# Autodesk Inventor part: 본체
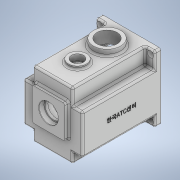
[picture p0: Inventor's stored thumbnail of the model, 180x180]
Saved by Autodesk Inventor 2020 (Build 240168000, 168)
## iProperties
Created: 2022-01
Part Number: 본체
Material: 일반
Document SubType Name: Modeling
Designer: user
Density: 1 g/cm^3
Appearance: 기본값
Author: user
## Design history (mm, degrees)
sketch "스케치5"
  geometry: L1 (-49, -55)-(49, -55); L2 (49, -55)-(49, 55); L3 (49, 55)-(-49, 55); L4 (-49, 55)-(-49, -55); L5 (-49, -55)-(49, 55); L6 (49, -55)-(-49, 55); 1 further point
  constraints: 12 end point, 2 midpoint, 2 parallel, 1 horizontal, 1 perpendicular
  dimensions: "d27" = 98 distance of L3.end L2.end; "d28" = 110 distance of L2.end L1.end
extrude "돌출6" new body sketch "스케치5" stored distance "d29" = 130; taper "d30" = 0 deg
sketch "스케치7"
  geometry: L1 (-49, 55)-(-49, -55) reference; L2 (-49, 55)-(-33, 55); L3 (-33, 55)-(-33, 28); L4 (-33, 28)-(-49, 28); L5 (-49, 28)-(-49, 55); L6 (49, 55)-(-49, 55) reference; L7 (49, 55)-(33, 55); L8 (33, 55)-(33, 28); L9 (33, 28)-(49, 28); L10 (49, 28)-(49, 55); L11 (49, -55)-(49, 55) reference; L12 (49, -55)-(33, -55); L13 (33, -55)-(33, -38); L14 (33, -38)-(49, -38); L15 (49, -38)-(49, -55); L16 (-49, -55)-(49, -55) reference; L17 (-49, -55)-(-33, -55); L18 (-33, -55)-(-33, -38); L19 (-33, -38)-(-49, -38); L20 (-49, -38)-(-49, -55); 6 further points
  constraints: 32 end point, 8 parallel, 4 horizontal, 4 perpendicular, 1 point on line
  dimensions: "d36" = 16 distance of L3.end L4.end; "d37" = 27 distance of L2.end L3.end; "d38" = 16 distance of L9.end L8.end; "d39" = 27 distance of L8.end L7.end; "d40" = 16 distance of L13.end L14.end; "d41" = 17 distance of L12.end L13.end; "d42" = 17 distance of L18.end L17.end
extrude "돌출8" cut sketch "스케치7" distance "d43" = 120; taper "d44" = 0 deg
sketch "스케치8"
  geometry: L1 (98, 0)-(0, 0) reference; L2 (49, 0)-(49, -40); L3 (49, -40)-(49, -89); C1 r 22.5 at (49, -40); C2 r 15 at (49, -89); 1 further point
  constraints: 4 end point, 2 centre point, 2 coincident, 1 midpoint, 1 point on line, 1 vertical
  dimensions: "d45" = 40 distance of L2.start L2.end; "d46" = 49 distance of L2.end L3.end; "d47" = 45 diameter of C1; "d48" = 30 diameter of C2
extrude "돌출9" join sketch "스케치8" distance "d49" = 5; taper "d50" = 0 deg
extrude "돌출10" join sketch "스케치8" distance "d51" = 10; taper "d52" = 0 deg
sketch "스케치9"
  geometry: L1 (0, 0)-(0, 11); L2 (33, -55)-(-33, -55) reference; L3 (0, -55)-(0, -5); L4 (0, 45)-(-23, 45); L5 (-23, 45)-(23, 45); L6 (23, 45)-(23, 33.249); L7 (-23, 33.249)-(-23, 45); A1 r 42 centre (0, -5) between (-25.375, 28.468) and (25.375, 28.468); A2 r 6 centre (-29, 33.249) between (-25.375, 28.468) and (-23, 33.249); A3 r 6 centre (29, 33.249) between (23, 33.249) and (25.375, 28.468); 4 further points
  constraints: 12 end point, 8 point on circle, 4 tangent, 3 centre point, 2 coincident, 2 horizontal, 2 point on line, 1 equal radius, 1 midpoint, 1 parallel, 1 perpendicular
  dimensions: "d63" = 50 distance of L3.start L3.end; "d64" = 84 diameter of A1; "d69" = 6 radius of A2 (derived)
extrude "돌출11" cut sketch "스케치9" distance "d70" = 121; taper "d71" = 0 deg
sketch "스케치10"
  geometry: L1 (-23, 33.249)-(-23, 45) reference; L2 (23, 45)-(23, 33.249) reference; L3 (-23, 45)-(23, 45) reference; L4 (26, 48)-(26, 33.249); L5 (-26, 33.249)-(-26, 48); L6 (-26, 48)-(26, 48); A1 r 42 centre (0, -5) between (-25.375, 28.468) and (25.375, 28.468) reference; A2 r 6 centre (-29, 33.249) between (-25.375, 28.468) and (-23, 33.249) reference; A3 r 42 centre (0, -5) between (-25.375, 28.468) and (25.375, 28.468) reference; A4 r 6 centre (29, 33.249) between (23, 33.249) and (25.375, 28.468) reference; A5 r 3 centre (29, 33.249) between (26, 33.249) and (27.188, 30.859); A6 r 45 centre (0, -5) between (-27.188, 30.859) and (27.188, 30.859); A7 r 3 centre (-29, 33.249) between (-27.188, 30.859) and (-26, 33.249); 3 further points
  constraints: 6 end point, 6 point on circle, 3 centre point, 5 other
  dimensions: "d72" = 3 distance between parallel lines of L3 L6
extrude "돌출12" cut sketch "스케치10" distance "d73" = 9; taper "d74" = 0 deg
sketch "스케치15"
  geometry: L1 (-33, -55)-(33, -55) reference; L2 (0, -55)-(0, 6); L3 (-27, -21)-(27, -21); L4 (27, -21)-(27, 33); L5 (27, 33)-(-27, 33); L6 (-27, 33)-(-27, -21); L7 (-27, -21)-(27, 33); L8 (27, -21)-(-27, 33); 1 further point
  constraints: 14 end point, 3 midpoint, 2 parallel, 1 horizontal, 1 perpendicular, 1 vertical
  dimensions: "d89" = 61 distance of L2.start L2.end; "d90" = 54 distance of L5.end L4.end; "d91" = 54 distance of L4.end L3.end
extrude "돌출14" join sketch "스케치15" distance "d92" = 7; taper "d93" = 0 deg
sketch "스케치16"
  geometry: L1 (27, -21)-(-27, -21) reference; L2 (0, -21)-(0, 6); C1 r 16 at (0, 6); 1 further point
  constraints: 2 end point, 1 centre point, 1 coincident, 1 midpoint, 1 vertical
  dimensions: "d94" = 27 distance of L2.start L2.end; "d95" = 32 diameter of C1
extrude "돌출15" cut sketch "스케치16" distance "d96" = 8.3; taper "d97" = 0 deg
chamfer "모따기2" distance "d98" = 0.8; stored, may be unused: second distance "d99" = 2, angle "d100" = 30 deg
sketch "스케치17"
  geometry: 1 further point
sketch "스케치18"
  geometry: L1 (33, -55)-(-33, -55) reference; L2 (0, -55)-(0, 6); L3 (23, 45)-(-23, 45) reference; C1 r 21 at (0, 6); C2 r 15 at (0, -25); 3 further points
  constraints: 2 centre point, 2 end point, 1 coincident, 1 midpoint, 1 vertical
  dimensions: "d101" = 61 distance of L2.start L2.end; "d102" = 42 diameter of C1; "d104" = 30 diameter of C2
extrude "돌출16" join sketch "스케치18" distance "d105" = 7; taper "d106" = 0 deg
sketch "스케치19"
  geometry: C1 r 16 at (0, 6) reference; C2 r 17.5 at (0, 6); A1 r 21 centre (0, 6) between (8.978, -12.984) and (-8.978, -12.984) reference; 1 further point
  constraints: 1 centre point, 1 coincident
  dimensions: "d107" = 35 diameter of C2
extrude "돌출17" cut sketch "스케치19" distance "d108" = 10; taper "d109" = 0 deg
sketch "스케치20"
  geometry: C1 r 14 at (0, 0); 1 further point
  constraints: 1 centre point
  dimensions: "d110" = 28 diameter of C1
extrude "돌출18" cut sketch "스케치20" distance "d111" = 10; taper "d112" = 0 deg
sketch "스케치21"
  geometry: 1 further point
sketch "스케치22"
  geometry: C1 r 11 at (0, -25); A1 r 15 centre (0, -25) between (-8.978, -12.984) and (8.978, -12.984) reference; 1 further point
  constraints: 1 centre point, 1 coincident
  dimensions: "d113" = 22 diameter of C1
extrude "돌출19" cut sketch "스케치22" distance "d114" = 7; taper "d115" = 0 deg
sketch "스케치23"
  geometry: C1 r 9.5 at (0, 0); 1 further point
  constraints: 1 centre point
  dimensions: "d116" = 19 diameter of C1
extrude "돌출20" cut sketch "스케치23" distance "d117" = 3; taper "d118" = 0 deg
sketch "스케치25"
  geometry: C1 r 15 at (23, -32) reference; C2 r 22.5 at (23, -81) reference; C3 r 15 at (23, -32); 1 further point
  constraints: 1 centre point, 1 coincident
  dimensions: "d120" = 30 diameter of C3
hole "구멍1" sketch "스케치25" at (23, -32) diameter "d121" = 20; stored, may be unused: countersink angle "d125" = 90 deg, drill point angle "d127" = 118 deg; dims "d122" = 4, "d123" = 30, "d124" = 5, "d126" = 20
sketch "스케치26"
  geometry: C1 r 22.5 at (0, 0) reference; 2 further points
  constraints: 1 coincident
hole "구멍2" sketch "스케치26" at (0, 0) diameter "d128" = 33.376; stored, may be unused: countersink angle "d132" = 90 deg, drill point angle "d134" = 118 deg; dims "d129" = 70, "d130" = 30, "d131" = 5, "d133" = 77.3
fillet "모깎기1" dims "d135" = 3
fillet "모깎기3" dims "d137" = 3
fillet "모깎기4" dims "d138" = 3
fillet "모깎기6" dims "d140" = 3
sketch "스케치27"
  geometry: 1 further point
sketch "스케치28"
  geometry: 1 further point
sketch "스케치29"
  geometry: 1 further point
sketch "스케치30"
  geometry: L1 (-49, 55)-(-49, -55) reference; L2 (-49, 55)-(-42, 55); L3 (-42, 55)-(-42, 48); L4 (-42, 48)-(-49, 48); L5 (-49, 48)-(-49, 55); L6 (-49, -55)-(49, -55) reference; L7 (-49, -55)-(-42, -55); L8 (-42, -55)-(-42, -48); L9 (-42, -48)-(-49, -48); L10 (-49, -48)-(-49, -55); L11 (49, -55)-(46, -55) reference; L12 (49, -55)-(42, -55); L13 (42, -55)-(42, -48); L14 (42, -48)-(49, -48); L15 (49, -48)-(49, -55); L16 (49, -55)-(49, 55) reference; L17 (49, 55)-(42, 55); L18 (42, 55)-(42, 48); L19 (42, 48)-(49, 48); L20 (49, 48)-(49, 55); 1 further point
  constraints: 32 end point, 8 parallel, 4 horizontal, 4 perpendicular
  dimensions: "d141" = 7 distance of L3.end L4.end; "d142" = 7 distance of L2.end L3.end; "d143" = 7 distance of L9.end L8.end; "d144" = 7 distance of L8.end L7.end; "d145" = 7 distance of L13.end L14.end; "d146" = 7 distance of L12.end L13.end; "d147" = 7 distance of L19.end L18.end; "d148" = 7 distance of L18.end L17.end
hole "구멍3" sketch "스케치30" at (-42, 48), (42, 48), (42, -48), (-42, -48) diameter "d149" = 10; stored, may be unused: countersink angle "d153" = 90 deg, drill point angle "d155" = 0 deg; dims "d150" = 70, "d151" = 30, "d152" = 5, "d154" = 10
fillet "모깎기7" dims "d156" = 3
sketch "스케치31"
  geometry: 1 further point
sketch "스케치32"
  geometry: L1 (-36, -1)-(-41.809, -1); L2 (-36, -9)-(-41.809, -9); A1 r 42 centre (0, -5) between (-25.375, 28.468) and (25.375, 28.468) reference; A2 r 4 centre (-36, -5) between (-36, -1) and (-36, -9); 1 further point
  constraints: 4 end point, 4 point on circle, 2 tangent, 1 centre point, 1 horizontal, 1 horizontal alignment, 1 parallel
  dimensions: "d157" = 36 distance of A2.centre A1.centre; "d158" = 8 diameter of A2
extrude "돌출21" join sketch "스케치32" stored distance "d159" = 3; taper "d160" = 0 deg
sketch "스케치33"
  geometry: 1 further point
sketch "스케치34"
  geometry: L1 (-130, 104)-(-130, 82) reference; L2 (-13, 107)-(-127, 107) reference; 2 further points
  constraints: 1 other
  dimensions: "d161" = 65 distance from line of L1 point (-65, 47); "d162" = 60 distance from line of L2 point (-65, 47)
feature "엠보싱1" sketch "스케치34" dims "d163" = 0.5, "d164" = 0
sketch "스케치35"
  geometry: A1 r 4 centre (-36, -5) between (-36, -9) and (-36, -1) reference; A2 r 4 centre (36, -5) between (36, -1) and (36, -9) reference; 3 further points
  constraints: 2 coincident
hole "구멍4" sketch "스케치35" at (-36, -5), (36, -5) diameter "d165" = 3.242; stored, may be unused: countersink angle "d169" = 90 deg, drill point angle "d171" = 118 deg; dims "d166" = 7, "d167" = 4, "d168" = 2, "d170" = 9
fillet "모깎기8" dims "d172" = 3
chamfer "모따기3" distance "d173" = 1; stored, may be unused: second distance "d174" = 2, angle "d175" = 45 deg
fillet "모깎기9" dims "d176" = 3
fillet "모깎기11" dims "d178" = 0.3
fillet "모깎기12" dims "d179" = 3
fillet "모깎기13" dims "d180" = 3
fillet "모깎기14" dims "d181" = 3
node "솔리드2"
mirror "미러1"
node "투영된 루프1"
node "투영된 루프2"
node "투영된 루프3"
feature "A9D066F2-1C7D-4E18-AEED-F7BC21143FA4" dims "d121" = 20, "d122" = 4, "d123" = 30, "d124" = 5, "d125" = 90 deg, "d126" = 20, "d127" = 118 deg
